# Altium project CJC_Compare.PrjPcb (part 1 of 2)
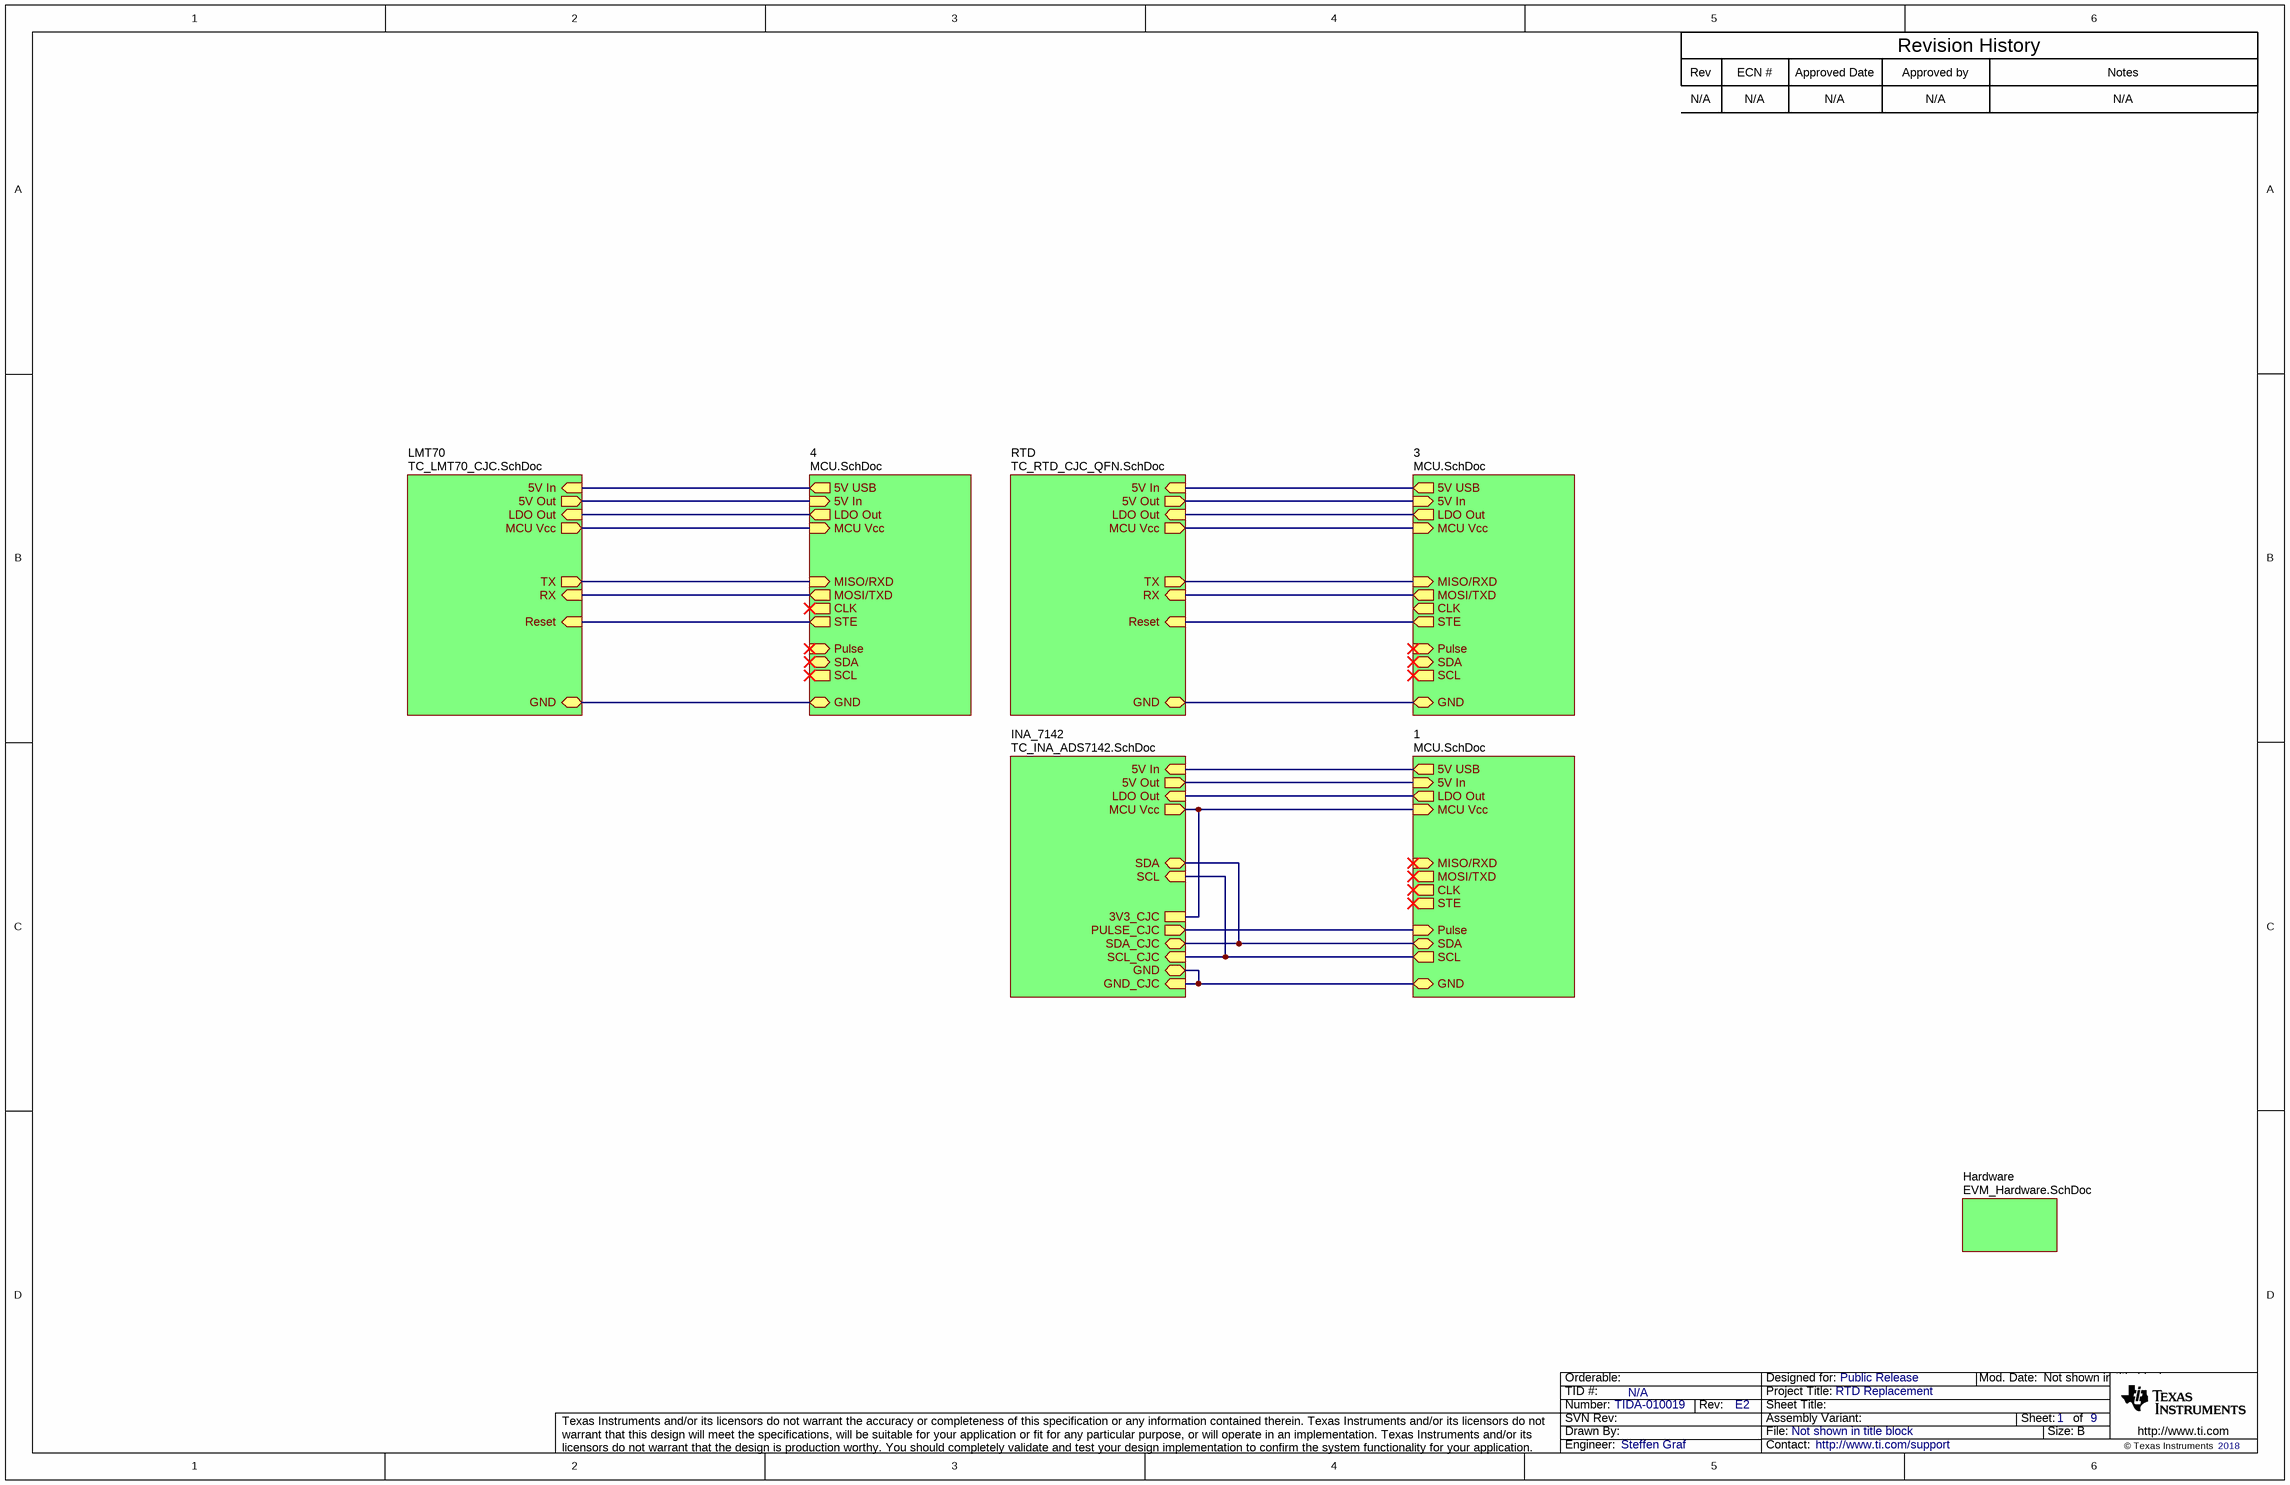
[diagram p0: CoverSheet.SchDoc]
CopyrightYear: 2018; PCB_Layout: SG; PCB_Rev: E2; PRJ_Customer: Public Release; PRJ_Engineer: Steffen Graf; PRJ_Number: TIDA-010019; PRJ_Title: RTD Replacement; SCH_Rev: E2; TechSupport: http://www.ti.com/support; TID: N/A
6 sheets, 304 parts. Net scope: strictly hierarchical (ports join the sheet entries above them; power ports are local).
Board file: TIDA-010019E2.PcbDoc
Sheets:
  CoverSheet.SchDoc
    Hardware = EVM_Hardware.SchDoc
    INA_7142 = TC_INA_ADS7142.SchDoc
    RTD = TC_RTD_CJC_QFN.SchDoc
    LMT70 = TC_LMT70_CJC.SchDoc
    1 = MCU.SchDoc
    3 = MCU.SchDoc
    4 = MCU.SchDoc

## Sheet CoverSheet.SchDoc
size 431 x 279 mm; Date: Not shown in title block; ApprovedBy: Not shown in title block; CheckedBy: Not shown in title block; Author: Not shown in title block; CompanyName: Not shown in title block; Engineer: Not shown in title block; Organization: Not shown in title block; Address1: Not shown in title block; Address2: Not shown in title block; Address3: Not shown in title block; Address4: Not shown in title block; DocumentNumber: 1; Revision: Use project parameter SCH_Rev; SheetNumber: 1; SheetTotal: 9; PageSetup: Record=PageOptions¦CenterHorizontal=True¦CenterVertical=True¦PrintScale=1.00¦XCorrection=1.00¦YCorrection=1.00¦PrintKind=0¦BorderSize=5000000¦LeftOffset=0¦BottomOffset=0¦Orientation=2¦PaperLength=1000¦PaperWidth=1000¦Scale=100¦PaperSource=15¦PrintQuality=600¦MediaType=1¦DitherType=10¦PaperKind=Letter¦PrintScaleMode=1

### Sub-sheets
1 = MCU.SchDoc: SDA (bidir), SCL (out), MISO/RXD (in), MOSI/TXD (out), Pulse (in), STE (out), CLK (out), 5V USB (out), MCU Vcc (in), 5V In (in), LDO Out (out), GND (bidir)
3 = MCU.SchDoc: SDA (bidir), SCL (out), MISO/RXD (in), MOSI/TXD (out), Pulse (in), STE (out), CLK (out), 5V USB (out), MCU Vcc (in), 5V In (in), LDO Out (out), GND (bidir)
4 = MCU.SchDoc: SDA (bidir), SCL (out), MISO/RXD (in), MOSI/TXD (out), Pulse (in), STE (out), CLK (out), 5V USB (out), MCU Vcc (in), 5V In (in), LDO Out (out), GND (bidir)
Hardware = EVM_Hardware.SchDoc: no entries
INA_7142 = TC_INA_ADS7142.SchDoc: SDA_CJC (bidir), GND_CJC (in), PULSE_CJC (out), 3V3_CJC, SDA (bidir), SCL_CJC (in), SCL (in), MCU Vcc (out), LDO Out (in), 5V Out (out), GND (bidir), 5V In (in)
LMT70 = TC_LMT70_CJC.SchDoc: TX (out), RX (in), Reset (in), MCU Vcc (out), LDO Out (in), 5V Out (out), 5V In (in), GND (bidir)
RTD = TC_RTD_CJC_QFN.SchDoc: Reset (in), TX (out), RX (in), LDO Out (in), 5V Out (out), 5V In (in), GND (bidir), MCU Vcc (out)

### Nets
3.3V: sheet INA_7142/3V3_CJC, sheet INA_7142/MCU Vcc, sheet 1/MCU Vcc
3.3V: sheet RTD/MCU Vcc, sheet 3/MCU Vcc  [a separate net that carries the same name]
3.3V: sheet LMT70/MCU Vcc, sheet 4/MCU Vcc  [a separate net that carries the same name]
GND: sheet INA_7142/GND_CJC, sheet INA_7142/GND, sheet 1/GND
GND: sheet RTD/GND, sheet 3/GND  [a separate net that carries the same name]
GND: sheet LMT70/GND, sheet 4/GND  [a separate net that carries the same name]
NetC83_1_1: sheet INA_7142/5V Out, sheet 1/5V In
NetC83_3_1: sheet RTD/5V Out, sheet 3/5V In
NetC83_4_1: sheet LMT70/5V Out, sheet 4/5V In
NetC84_1_1: sheet INA_7142/LDO Out, sheet 1/LDO Out
NetC84_3_1: sheet RTD/LDO Out, sheet 3/LDO Out
NetC84_4_1: sheet LMT70/LDO Out, sheet 4/LDO Out
NetC89_1_1: sheet INA_7142/5V In, sheet 1/5V USB
NetC89_3_1: sheet RTD/5V In, sheet 3/5V USB
NetC89_4_1: sheet LMT70/5V In, sheet 4/5V USB
NetJ8_10: sheet LMT70/TX, sheet 4/MISO/RXD
NetJ8_12: sheet LMT70/RX, sheet 4/MOSI/TXD
NetJ8_14: sheet LMT70/Reset, sheet 4/STE
NetJ22_14: sheet INA_7142/SCL_CJC, sheet INA_7142/SCL, sheet 1/SCL
NetJ24_10: sheet RTD/TX, sheet 3/MISO/RXD
NetJ24_12: sheet RTD/RX, sheet 3/MOSI/TXD
NetJ24_14: sheet RTD/Reset, sheet 3/STE
NetJ36_1: sheet INA_7142/PULSE_CJC, sheet 1/Pulse
NetJ36_2: sheet INA_7142/SDA_CJC, sheet INA_7142/SDA, sheet 1/SDA

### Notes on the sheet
- Rev
- N/A
- ECN #
- Approved Date
- Approved by
- Revision History
- Notes

## Sheet EVM_Hardware.SchDoc
size 431 x 279 mm; Date: Not shown in title block; ApprovedBy: Not shown in title block; CheckedBy: Not shown in title block; Author: Not shown in title block; CompanyName: Not shown in title block; Engineer: Not shown in title block; Organization: Not shown in title block; Address1: Not shown in title block; Address2: Not shown in title block; Address3: Not shown in title block; Address4: Not shown in title block; DocumentNumber: 9; Revision: Use project parameter SCH_Rev; SheetNumber: 9; SheetTotal: 9; PageSetup: Record=PageOptions¦CenterHorizontal=True¦CenterVertical=True¦PrintScale=1.00¦XCorrection=1.00¦YCorrection=1.00¦PrintKind=0¦BorderSize=5000000¦LeftOffset=0¦BottomOffset=0¦Orientation=2¦PaperLength=1000¦PaperWidth=1000¦Scale=100¦PaperSource=15¦PrintQuality=600¦MediaType=1¦DitherType=10¦PaperKind=Letter¦PrintScaleMode=1
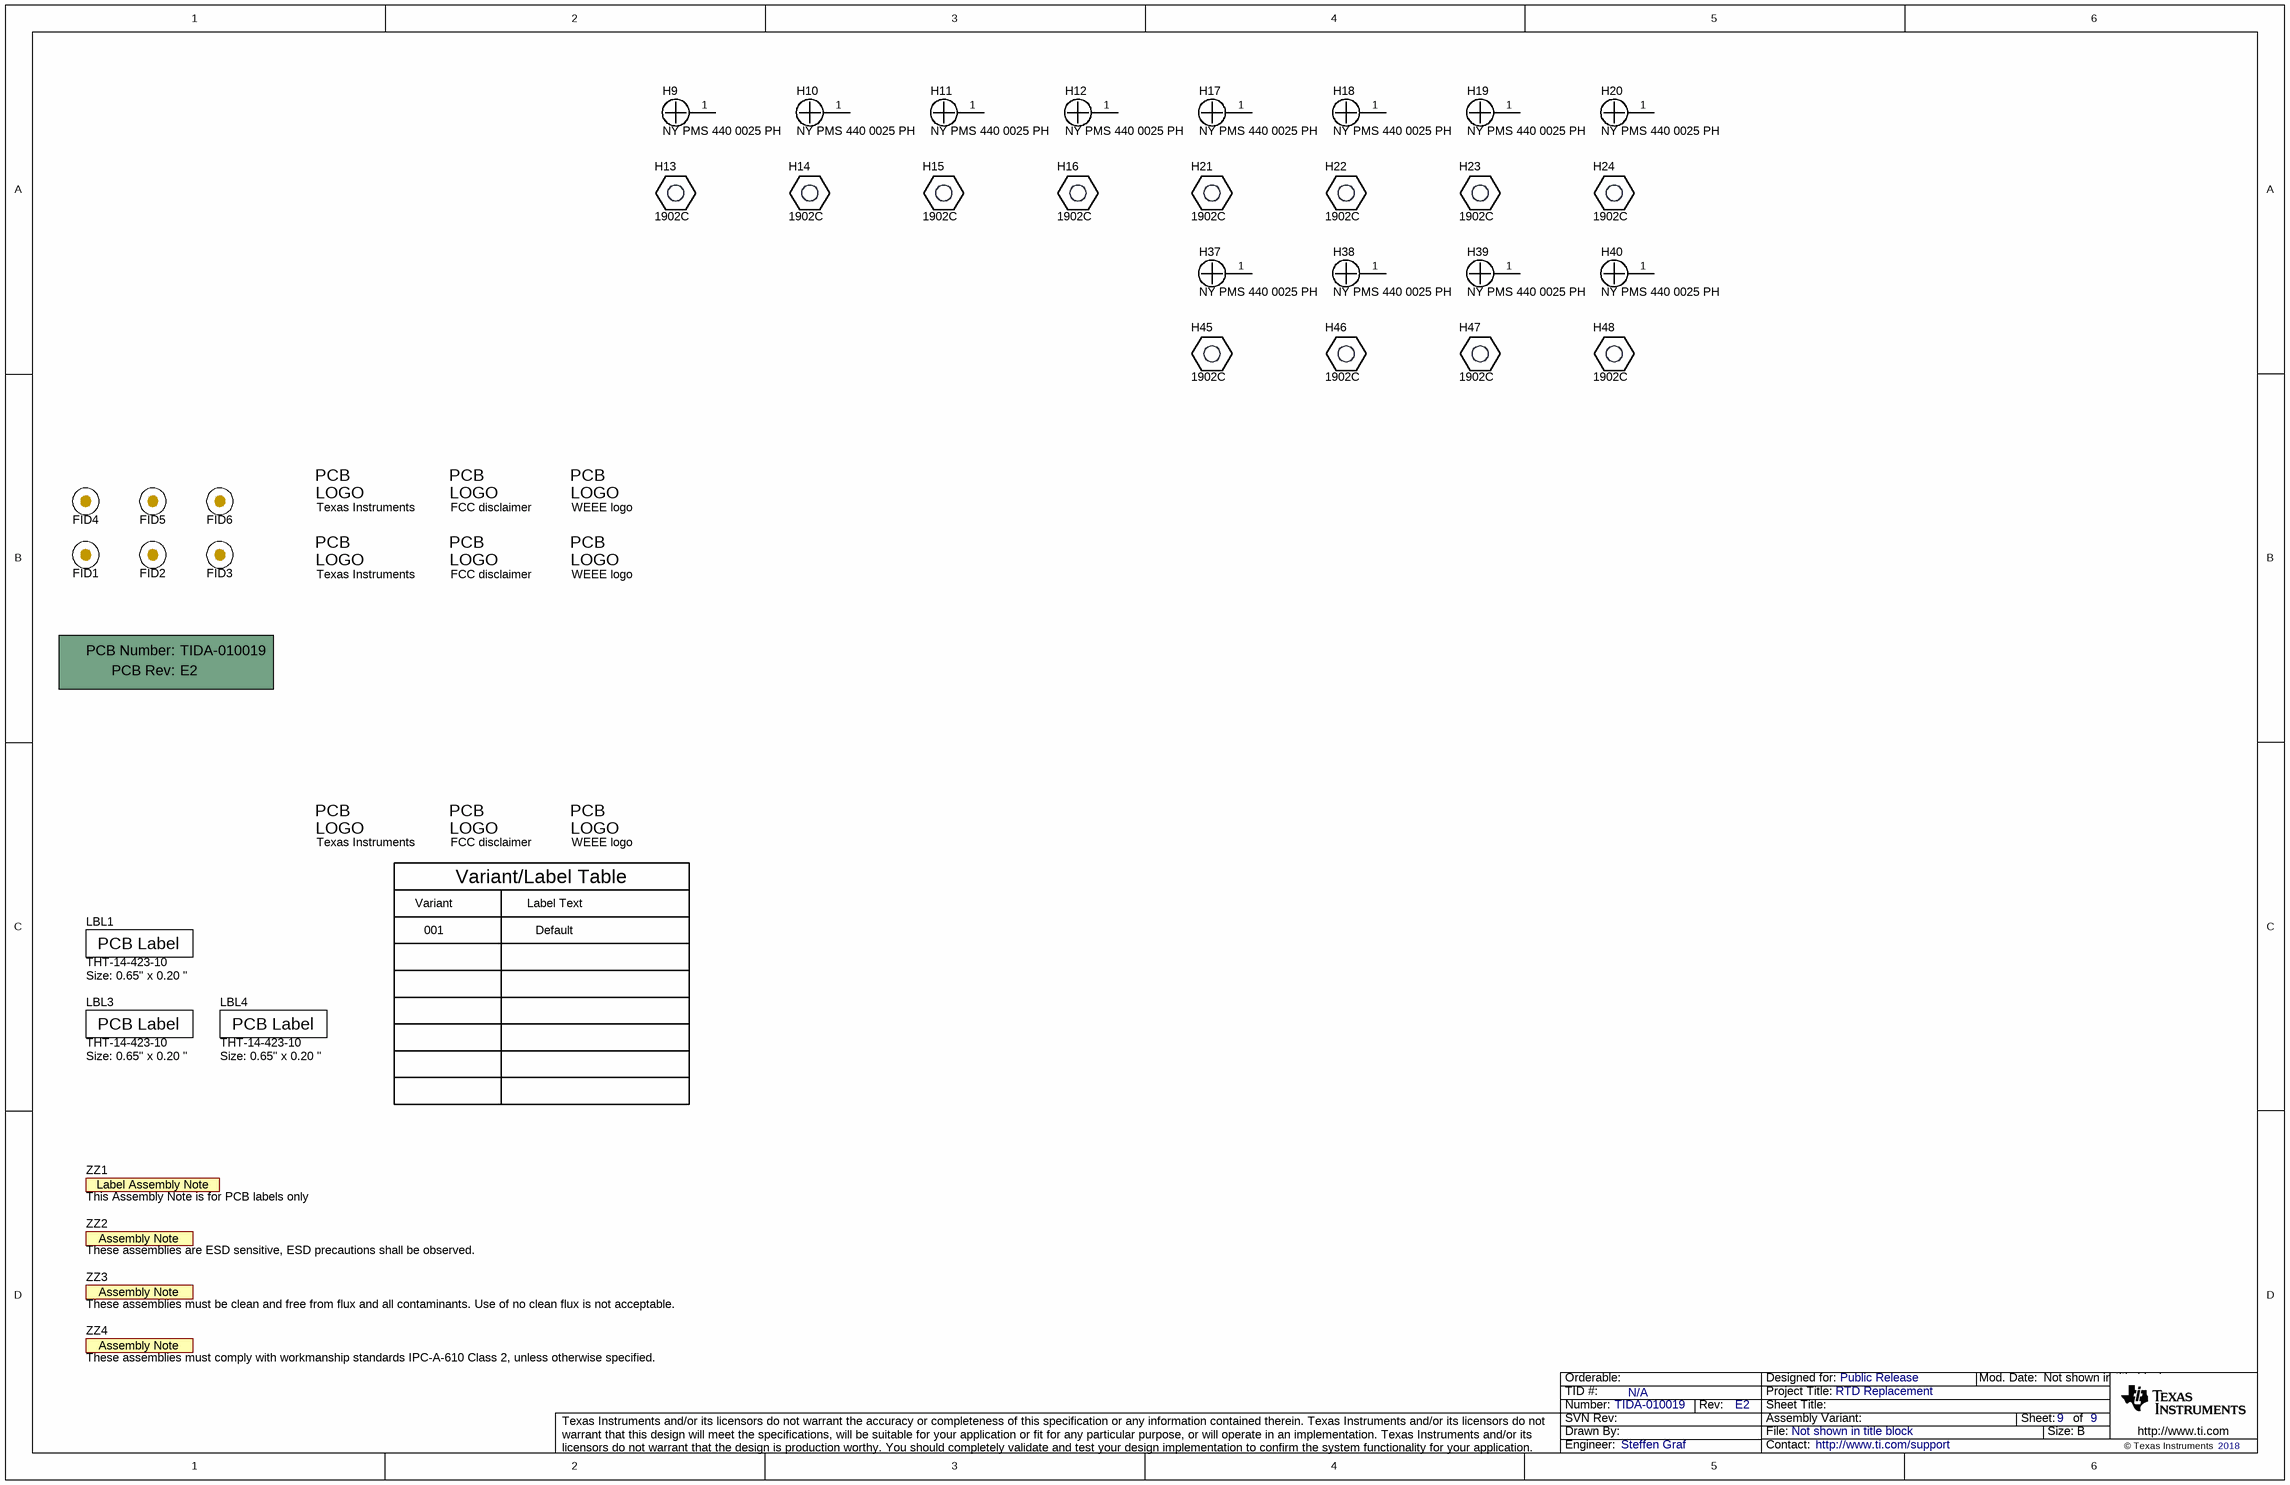
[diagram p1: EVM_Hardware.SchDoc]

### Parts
!PCB  Printed Circuit Board  (value not drawn)  (mechanical)
FID1  Fiducial  [Fiducial10-20]  (value not drawn)
FID2  Fiducial  [Fiducial10-20]  (value not drawn)
FID3  Fiducial  [Fiducial10-20]  (value not drawn)
FID4  Fiducial  [Fiducial10-20]  (value not drawn)
FID5  Fiducial  [Fiducial10-20]  (value not drawn)
FID6  Fiducial  [Fiducial10-20]  (value not drawn)
H9  NY PMS 440 0025 PH  [NY PMS 440 0025 PH]
H10  NY PMS 440 0025 PH  [NY PMS 440 0025 PH]
H11  NY PMS 440 0025 PH  [NY PMS 440 0025 PH]
H12  NY PMS 440 0025 PH  [NY PMS 440 0025 PH]
H13  1902C  [Keystone_1902C]
H14  1902C  [Keystone_1902C]
H15  1902C  [Keystone_1902C]
H16  1902C  [Keystone_1902C]
H17  NY PMS 440 0025 PH  [NY PMS 440 0025 PH]
H18  NY PMS 440 0025 PH  [NY PMS 440 0025 PH]
H19  NY PMS 440 0025 PH  [NY PMS 440 0025 PH]
H20  NY PMS 440 0025 PH  [NY PMS 440 0025 PH]
H21  1902C  [Keystone_1902C]
H22  1902C  [Keystone_1902C]
H23  1902C  [Keystone_1902C]
H24  1902C  [Keystone_1902C]
H37  NY PMS 440 0025 PH  [NY PMS 440 0025 PH]
H38  NY PMS 440 0025 PH  [NY PMS 440 0025 PH]
H39  NY PMS 440 0025 PH  [NY PMS 440 0025 PH]
H40  NY PMS 440 0025 PH  [NY PMS 440 0025 PH]
H45  1902C  [Keystone_1902C]
H46  1902C  [Keystone_1902C]
H47  1902C  [Keystone_1902C]
H48  1902C  [Keystone_1902C]
LBL1  THT-14-423-10  Note: Size: 0.65" x 0.20 "  [Label_650x200]
LBL3  THT-14-423-10  Note: Size: 0.65" x 0.20 "  [Label_650x200]
LBL4  THT-14-423-10  Note: Size: 0.65" x 0.20 "  [Label_650x200]
Logo1  Texas Instruments  [TI_Stacked_Overlay_Small]  (no BOM)
Logo2  Texas Instruments  [TI_Stacked_Overlay_Small]  (no BOM)
Logo3  FCC disclaimer  [FCC_disclaimer]  (no BOM)
Logo4  WEEE logo  [WEEE_Minimum]  (no BOM)
Logo5  FCC disclaimer  [FCC_disclaimer]  (no BOM)
Logo6  WEEE logo  [WEEE_Minimum]  (no BOM)
Logo16  Texas Instruments  [TI_Stacked_Overlay_Small]  (no BOM)
Logo17  FCC disclaimer  [FCC_disclaimer]  (no BOM)
Logo18  WEEE logo  [WEEE_Minimum]  (no BOM)
ZZ1  This Assembly Note is for PCB labels only  [AssemblyNoteLabel]  (no BOM)
ZZ2  These assemblies are ESD sensitive, ESD precautions shall be observed.  [AssemblyNote]  (no BOM)
ZZ3  These assemblies must be clean and free from flux and all contaminants. Use of no clean flux is not acceptable.  [AssemblyNote]  (no BOM)
ZZ4  These assemblies must comply with workmanship standards IPC-A-610 Class 2, unless otherwise specified.  [AssemblyNote]  (no BOM)

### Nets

Not connected (* = marked no-connect by the designer): H9 1; H10 1; H11 1; H12 1; H17 1; H18 1; H19 1; H20 1; H37 1; H38 1; H39 1; H40 1

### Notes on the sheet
- Variant
- Variant/Label Table
- Label Text
- 001
- Default

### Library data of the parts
!PCB = CMP-0003618-2: Manufacturer: Any; PartNumber: TIDA-010019
FID1-FID6 = CMP-0077181-1: Fiducial mark.  There is nothing to buy or mount.
H9-H12 H17-H20 H37-H40 = CMP-0003617-1: Machine Screw, Round, #4-40 x 1/4, Nylon, Philips panhead; Manufacturer: B&F Fastener Supply; CompType: Hardware
H13-H16 H21-H24 H45-H48 = CMP-0003610-1: Standoff, Hex, 0.5"L #4-40 Nylon; Manufacturer: Keystone; CompType: Hardware
LBL1 LBL3 LBL4 = CMP-0003625-1: Thermal Transfer Printable Labels, 0.650" W x 0.200" H - 10,000 per roll; Manufacturer: Brady; CompType: Label
Logo1 Logo2 Logo16 = CMP-0074838-1: Texas Instrument Corporate Signature; SymbolCreator: a0412235; Lib Reference: TI_Logo; Library Reference: Logo
Logo3 Logo5 Logo17 = CMP-0074847-1: FCC_disclaimer; Library Reference: Logo
Logo4 Logo6 Logo18 = CMP-0074769-1
ZZ1 = CMP-0003616-3
ZZ2 = CMP-0077236-1
ZZ3 = CMP-0077237-1
ZZ4 = CMP-0077238-1

## Sheet TC_INA_ADS7142.SchDoc
size 431 x 279 mm; Date: Not shown in title block; ApprovedBy: Not shown in title block; CheckedBy: Not shown in title block; Author: Not shown in title block; CompanyName: Not shown in title block; Engineer: Not shown in title block; Organization: Not shown in title block; Address1: Not shown in title block; Address2: Not shown in title block; Address3: Not shown in title block; Address4: Not shown in title block; DocumentNumber: 5; Revision: Use project parameter SCH_Rev; SheetNumber: 5; SheetTotal: 9; PageSetup: Record=PageOptions¦CenterHorizontal=True¦CenterVertical=True¦PrintScale=1.00¦XCorrection=1.00¦YCorrection=1.00¦PrintKind=0¦BorderSize=5000000¦LeftOffset=0¦BottomOffset=0¦Orientation=2¦PaperLength=1000¦PaperWidth=1000¦Scale=100¦PaperSource=15¦PrintQuality=600¦MediaType=1¦DitherType=10¦PaperKind=Letter¦PrintScaleMode=1
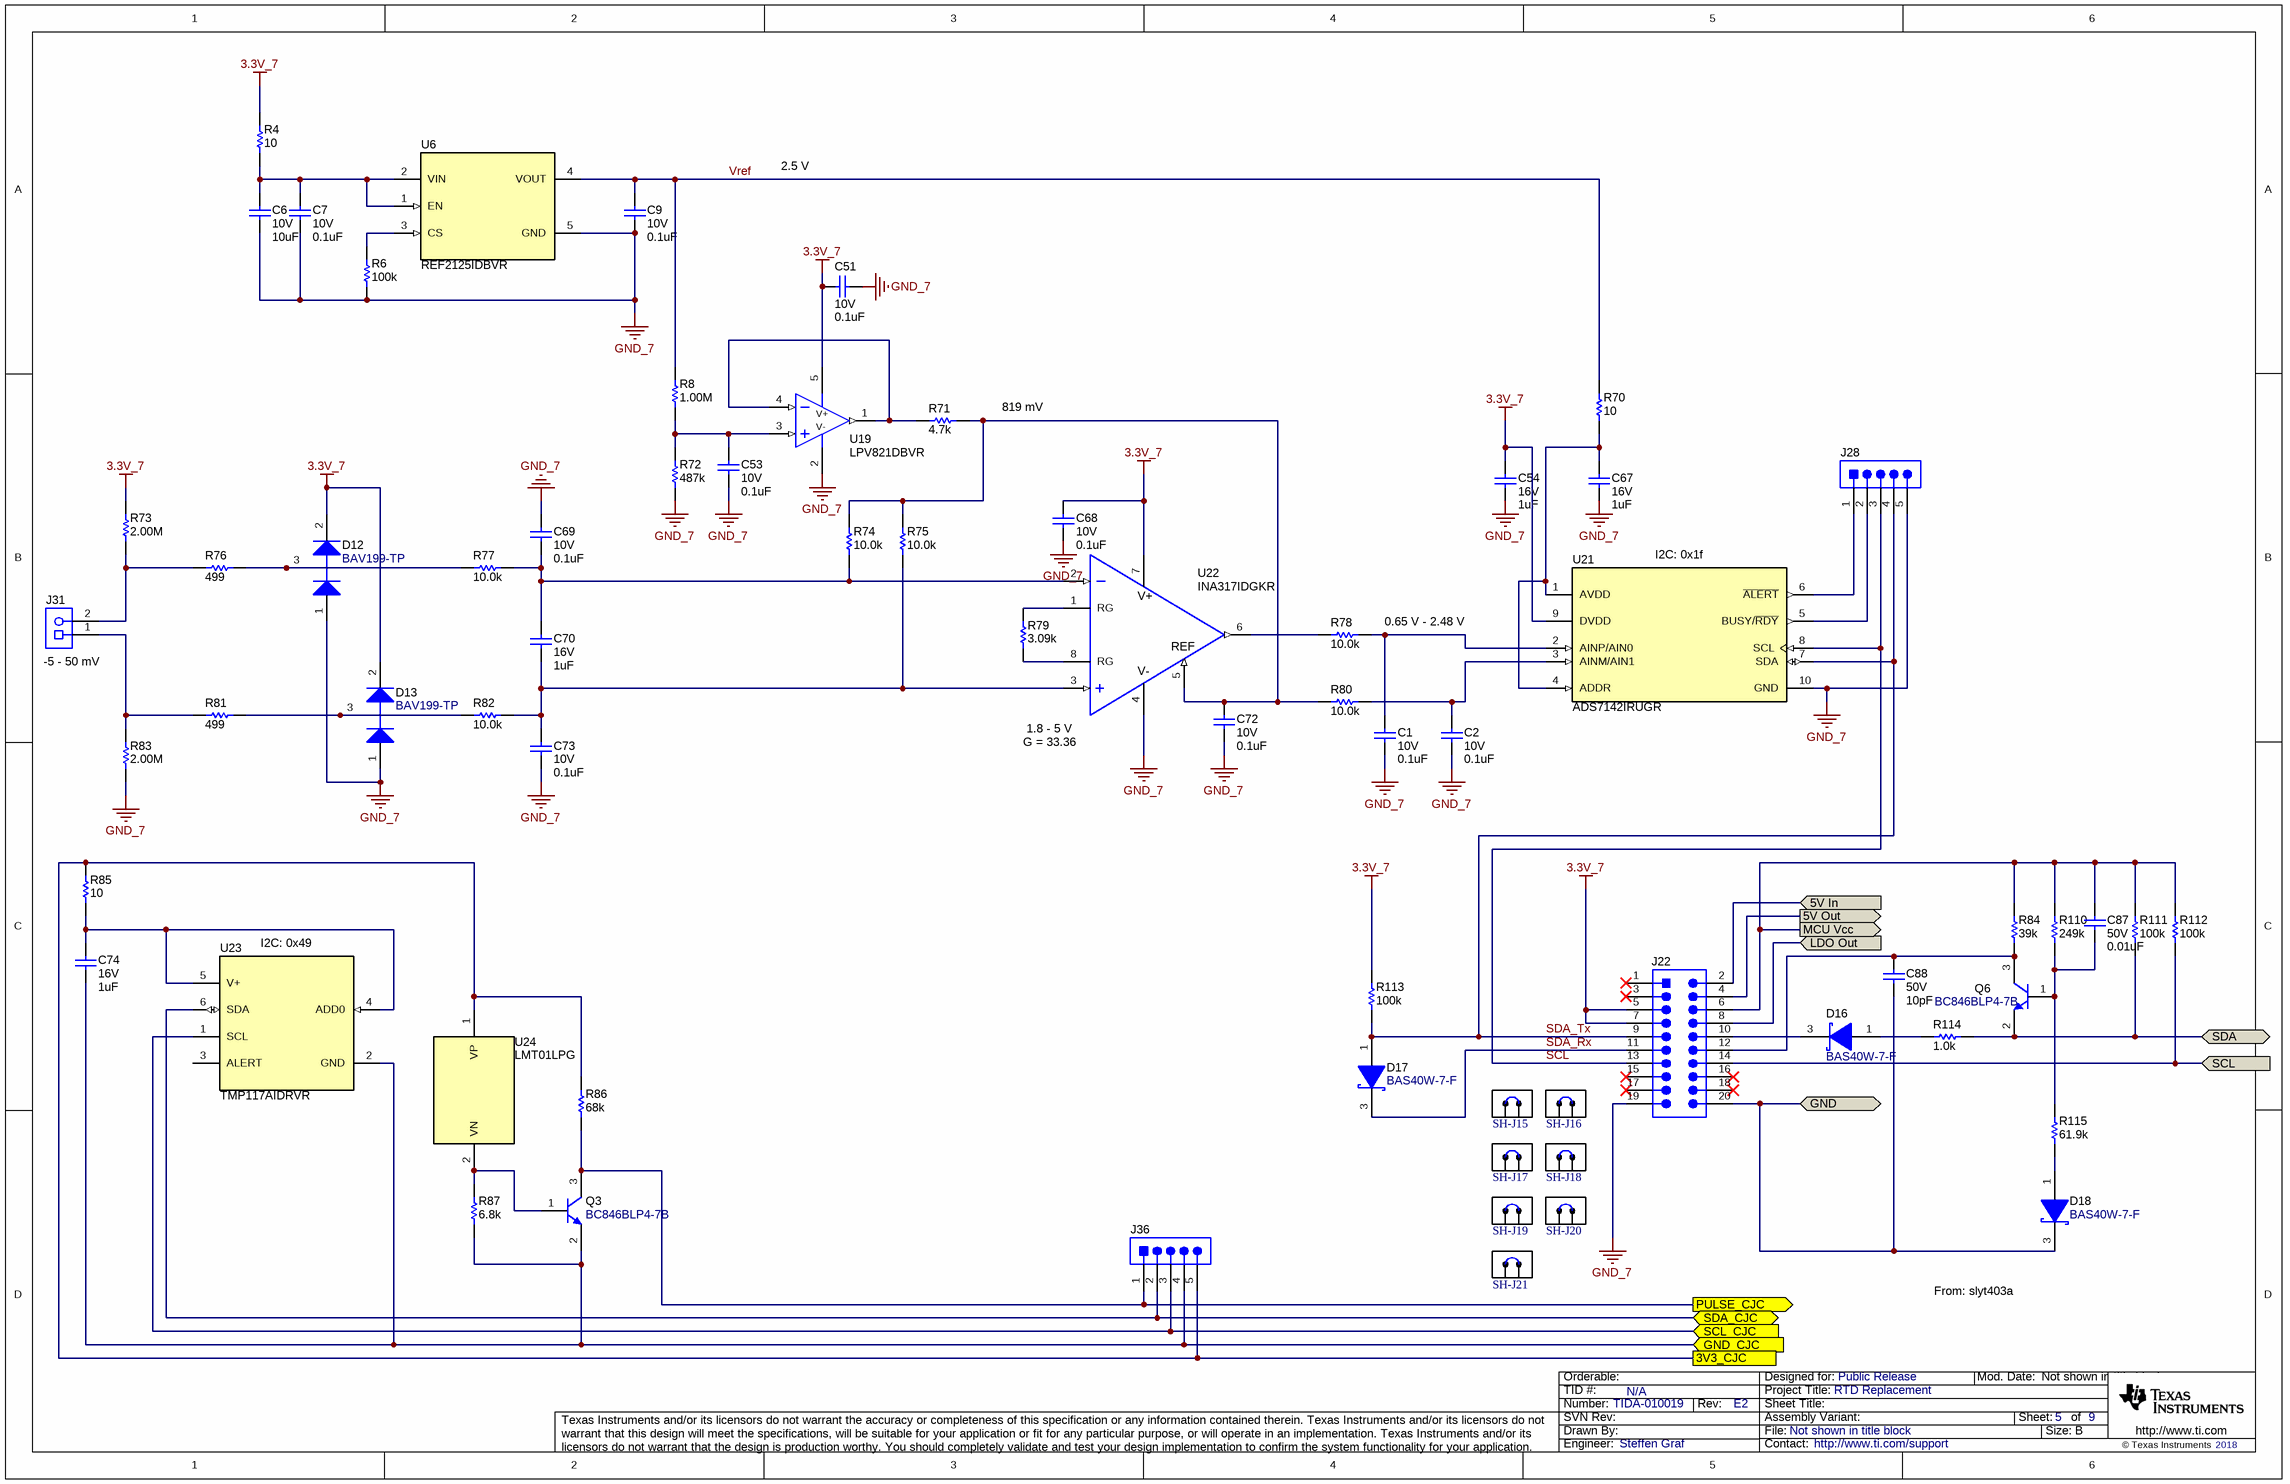
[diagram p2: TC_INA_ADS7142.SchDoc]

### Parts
C1  VDC_V: 10V  ValueDisplayed: 0.1uF  [0603]  (hidden comment: 885012206020)
C2  VDC_V: 10V  ValueDisplayed: 0.1uF  [0603]  (hidden comment: 885012206020)
C6  VDC_V: 10V  ValueDisplayed: 10uF  [0805_HV]  (hidden comment: 885012207026)
C7  VDC_V: 10V  ValueDisplayed: 0.1uF  [0603]  (hidden comment: 885012206020)
C9  VDC_V: 10V  ValueDisplayed: 0.1uF  [0603]  (hidden comment: 885012206020)
C51  VDC_V: 10V  ValueDisplayed: 0.1uF  [0603]  (hidden comment: 885012206020)
C53  VDC_V: 10V  ValueDisplayed: 0.1uF  [0603]  (hidden comment: 885012206020)
C54  VDC_V: 16V  ValueDisplayed: 1uF  [0603]  (hidden comment: 885012106017)
C67  VDC_V: 16V  ValueDisplayed: 1uF  [0603]  (hidden comment: 885012106017)
C68  VDC_V: 10V  ValueDisplayed: 0.1uF  [0603]  (hidden comment: 885012206020)
C69  VDC_V: 10V  ValueDisplayed: 0.1uF  [0603]  (hidden comment: 885012206020)
C70  VDC_V: 16V  ValueDisplayed: 1uF  [0603]  (hidden comment: GCM188R71C105MA64D)
C72  VDC_V: 10V  ValueDisplayed: 0.1uF  [0603]  (hidden comment: 885012206020)
C73  VDC_V: 10V  ValueDisplayed: 0.1uF  [0603]  (hidden comment: 885012206020)
C74  VDC_V: 16V  ValueDisplayed: 1uF  [0603]  (hidden comment: 885012106017)
C87  VDC_V: 50V  ValueDisplayed: 0.01uF  [0402]  (hidden comment: GCM155R71H103KA55D)
C88  VDC_V: 50V  ValueDisplayed: 10pF  [0402]  (hidden comment: 885012005055)
D12  BAV199-TP  [SOT-23L]
D13  BAV199-TP  [SOT-23L]
D16  BAS40W-7-F  [SOT-323]
D17  BAS40W-7-F  [SOT-323]
D18  BAS40W-7-F  [SOT-323]
J22  PRPC010DAAN-RC  [Sullins_xxxC010DAAN]  (value not drawn)
J28  61300511121  [Wurth_61300511121]  (value not drawn)
J31  691210910002  [Wurth_691210910002]  (value not drawn)
J36  61300511121  [Wurth_61300511121]  (value not drawn)
Q3  BC846BLP4-7B  [X2-DFN1006-3]
Q6  BC846BLP4-7B  [X2-DFN1006-3]
R4  ValueDisplayed: 10  [0402]  (hidden comment: CRCW040210R0JNED)
R6  ValueDisplayed: 100k  [0402]  (hidden comment: CRCW0402100KFKED)
R8  ValueDisplayed: 1.00M  [0603]  (hidden comment: RMCF0603FG1M00)
R70  ValueDisplayed: 10  [0402]  (hidden comment: CRCW040210R0JNED)
R71  ValueDisplayed: 4.7k  [0402]  (hidden comment: CRCW04024K70JNED)
R72  ValueDisplayed: 487k  [0603]  (hidden comment: CRCW0603487KFKEA)
R73  ValueDisplayed: 2.00M  [0402]  (hidden comment: CRCW04022M00FKED)
R74  ValueDisplayed: 10.0k  [0603]  (hidden comment: CRCW060310K0FKEA)
R75  ValueDisplayed: 10.0k  [0603]  (hidden comment: CRCW060310K0FKEA)
R76  ValueDisplayed: 499  [0402]  (hidden comment: CRCW0402499RFKED)
R77  ValueDisplayed: 10.0k  [0402]  (hidden comment: CRCW040210K0FKED)
R78  ValueDisplayed: 10.0k  [0603]  (hidden comment: CRCW060310K0FKEA)
R79  ValueDisplayed: 3.09k  [0603]  (hidden comment: CRCW06033K09FKEA)
R80  ValueDisplayed: 10.0k  [0603]  (hidden comment: CRCW060310K0FKEA)
R81  ValueDisplayed: 499  [0402]  (hidden comment: CRCW0402499RFKED)
R82  ValueDisplayed: 10.0k  [0402]  (hidden comment: CRCW040210K0FKED)
R83  ValueDisplayed: 2.00M  [0402]  (hidden comment: CRCW04022M00FKED)
R84  ValueDisplayed: 39k  [0402S]  (hidden comment: CRCW040239K0JNED)
R85  ValueDisplayed: 10  [0402]  (hidden comment: CRCW040210R0JNED)
R86  ValueDisplayed: 68k  [0402]  (hidden comment: CRCW040268K0JNED)
R87  ValueDisplayed: 6.8k  [0402]  (hidden comment: CRCW04026K80JNED)
R110  ValueDisplayed: 249k  [0402]  (hidden comment: CRCW0402249KFKED)
R111  ValueDisplayed: 100k  [0402]  (hidden comment: CRCW0402100KJNED)
R112  ValueDisplayed: 100k  [0402]  (hidden comment: CRCW0402100KJNED)
R113  ValueDisplayed: 100k  [0402]  (hidden comment: CRCW0402100KJNED)
R114  ValueDisplayed: 1.0k  [0402]  (hidden comment: CRCW04021K00JNED)
R115  ValueDisplayed: 61.9k  [0402]  (hidden comment: CRCW040261K9FKED)
SH-J15  60900213421  [Wurth_60900213421]  (value not drawn)
SH-J16  60900213421  [Wurth_60900213421]  (value not drawn)
SH-J17  60900213421  [Wurth_60900213421]  (value not drawn)
SH-J18  60900213421  [Wurth_60900213421]  (value not drawn)
SH-J19  60900213421  [Wurth_60900213421]  (value not drawn)
SH-J20  60900213421  [Wurth_60900213421]  (value not drawn)
SH-J21  60900213421  [Wurth_60900213421]  (value not drawn)
U6  REF2125IDBVR  [DBV0005A_N]
U19  LPV821DBVR  [DBV0005A_N]
U21  ADS7142IRUGR  [RUG0010A]
U22  INA317IDGKR  [DGK0008A_N]
U23  TMP117AIDRVR  [DRV0006B]
U24  LMT01LPG  [LPG0002A]

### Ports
3V3_CJC, 5V In (in), 5V Out (out), GND (bidir), GND_CJC (in), LDO Out (in), MCU Vcc (out), PULSE_CJC (out), SCL (in), SCL_CJC (in), SDA (bidir), SDA_CJC (bidir)

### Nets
3.3V: C87.1 J22.6 J36.5 R84.2 R85.1 R86.2 R110.2 R111.2 R112.2 U24.1(VP) ; port 3V3_CJC, port MCU Vcc
3.3V_7: C51.1 C54.1 C68.1 D12.2(K) D13.2(K) J22.5 J22.7 R4.2 R73.2 R113.2 U19.5(V+) U21.9(DVDD) U22.7(V+)
GND: C74.2 C88.2 D18.3(K) J22.20 J36.4 Q3.2(E) R87.1 U23.2(GND) ; port GND_CJC, port GND
GND_7: C1.2 C2.2 C6.2 C7.2 C9.2 C51.2 C53.2 C54.2 C67.2 C68.2 C69.1 C72.2 C73.2 D12.1(A) D13.1(A) J22.19 J28.5 R6.1 R72.1 R83.1 U6.5(GND) U19.2(V-) U21.10(GND) U22.4(V-)
SCL: J22.13 J28.3 U21.8(SCL)  [project net SCL_5]
SDA_Rx: D17.3(K) J22.11  [project net SDA_Rx_5]
SDA_Tx: D17.1(A) J22.9 J28.4 R113.1 U21.7(SDA)  [project net SDA_Tx_5]
Vref: C9.1 R8.2 R70.2 U6.4(VOUT)  [project net Vref_5]
NetC1_1: C1.1 R78.2 U21.2(AINP/AIN0)
NetC2_1: C2.1 R80.2 U21.3(AINM/AIN1)
NetC6_1: C6.1 C7.1 R4.1 U6.1(EN) U6.2(VIN)
NetC53_1: C53.1 R8.1 R72.2 U19.3(IN+)
NetC67_1: C67.1 R70.1 U21.1(AVDD) U21.4(ADDR)
NetC69_2: C69.2 C70.1 R74.1 R77.1 U22.2(IN-)
NetC70_2: C70.2 C73.1 R75.1 R82.1 U22.3(IN+)
NetC72_1: C72.1 R71.1 R74.2 R75.2 R80.1 U22.5(REF)
NetC74_1: C74.1 R85.2 U23.4(ADD0) U23.5(V+)
NetC83_1_1: J22.4 ; port 5V Out
NetC84_1_1: J22.8 ; port LDO Out
NetC87_2: C87.2 Q6.1(B) R110.1 R115.2
NetC88_1: C88.1 J22.12 Q6.3(C) R84.1
NetC89_1_1: J22.2 ; port 5V In
NetD12_3: D12.3(C) R76.1 R77.2
NetD13_3: D13.3(C) R81.1 R82.2
NetD16_1: D16.1(A) R114.1
NetD16_3: D16.3(K) J22.10
NetD18_1: D18.1(A) R115.1
NetJ22_14: J22.14 J36.3 R112.1 U23.1(SCL) ; port SCL_CJC, port SCL
NetJ28_1: J28.1 U21.6(~{ALERT})
NetJ28_2: J28.2 U21.5(BUSY/~{RDY})
NetJ31_1: J31.1 R81.2 R83.2
NetJ31_2: J31.2 R73.1 R76.2
NetJ36_1: J36.1 Q3.3(C) R86.1 ; port PULSE_CJC
NetJ36_2: J36.2 Q6.2(E) R111.1 R114.2 U23.6(SDA) ; port SDA_CJC, port SDA
NetQ3_1: Q3.1(B) R87.2 U24.2(VN)
NetR6_2: R6.2 U6.3(CS)
NetR71_2: R71.2 U19.1(OUT) U19.4(IN-)
NetR78_1: R78.1 U22.6(OUT)
NetR79_1: R79.1 U22.8(RG)
NetR79_2: R79.2 U22.1(RG)

Not connected (* = marked no-connect by the designer): J22 1* 3* 15* 16* 17* 18*; U23 3(ALERT)

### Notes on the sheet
- 2.5 V
- (near R71) 819 mV
- (near U21) I2C: 0x1f
- (near R78) 0.65 V - 2.48 V
- (near J31) -5 - 50 mV
- (near U22) 1.8 - 5 V
- (near U22) G = 33.36
- (near U23) I2C: 0x49
- From: slyt403a

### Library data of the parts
C1 C2 C7 C9 C51 C53 C68 C69 C72 C73 = CMP-0064931-4: CAP, CERM, 0.1 uF, 10 V,+/- 10%, X7R, 0603; Manufacturer: Wurth Elektronik; TaMin_C: -55°C; Polarized: N; SizeAreaWB_mm2: 4.68; Value1: Unknown; U/M: EA; Value: 0.1uF; TaMax_C: 125°C; SizeZ_mm: 1; SizeX_mm: 1.6; SizeY_mm: 0.8; SizeArea_mm2: 1.28; Cap_F: 100nF; AEC Category: Q200
C6 = CMP-0007691-2: CAP, CERM, 10 uF, 10 V, +/- 10%, X7R, 0805; Manufacturer: Wurth Elektronik; TaMin_C: -55°C; Polarized: N; SizeAreaWB_mm2: 6.75; Value1: Unknown; U/M: EA; Value: 10uF; TaMax_C: 125°C; SizeZ_mm: 1.45; SizeX_mm: 2; SizeY_mm: 1.25; Cap_Case: 0805; SizeArea_mm2: 2.5; Cap_F: 10µF; AEC Category: Q200
C54 C67 C74 = CMP-0006824-5: CAP, CERM, 1 uF, 16 V, +/- 20%, X5R, 0603; Manufacturer: Wurth Elektronik; TaMin_C: -55°C; Polarized: N; SizeAreaWB_mm2: 4.68; Value1: Unknown; U/M: EA; Value: 1uF; TaMax_C: 85°C; SizeZ_mm: 1; SizeX_mm: 1.6; SizeY_mm: 0.8; SizeArea_mm2: 1.28; Cap_F: 1µF; AEC Category: Q200
C70 = CMP-0007137-5: CAP, CERM, 1 uF, 16 V, +/- 20%, X7R, AEC-Q200 Grade 1, 0603; Manufacturer: MuRata; TaMin_C: -55°C; Polarized: N; SizeAreaWB_mm2: 4.68; Value1: Unknown; U/M: EA; Value: 1uF; TaMax_C: 125°C; SizeZ_mm: 1; SizeX_mm: 1.6; SizeY_mm: 0.8; SizeArea_mm2: 1.28; AEC Qualified: Y; Cap_F: 1µF; AEC Category: Q200
C87 = CMP-0006355-2: CAP, CERM, 0.01 uF, 50 V, +/- 10%, C0G/NP0, 0402; Manufacturer: MuRata; TaMin_C: -55°C; Polarized: N; SizeAreaWB_mm2: 3; Value1: Unknown; U/M: EA; Value: 0.01uF; TaMax_C: 125°C; SizeZ_mm: 0.6; SizeX_mm: 1; SizeY_mm: 0.5; Cap_F: 10nF; AEC Category: Q200
C88 = CMP-0006215-2: CAP, CERM, 10 pF, 50 V, +/- 5%, C0G/NP0, 0402; Manufacturer: Wurth Elektronik; TaMin_C: -55°C; Polarized: N; SizeAreaWB_mm2: 3; Value1: Unknown; U/M: EA; Value: 10pF; TaMax_C: 125°C; SizeZ_mm: 0.6; SizeX_mm: 1; SizeY_mm: 0.5; AEC Category: Q200
D12 D13 = CMP-0076968-2: Diode, Switching, 70 V, 0.215 A, SOT-23; Manufacturer: Micro Commercial Components; SizeAreaWB_mm2: 14.0; Vr_V: 70V; SizeArea_mm2: 7.5; TJmax_C: 150°C; AEC Category: Q101; Value: 70V; SizeZ_mm: 1.1; Green_REACh: Incomplete; Io_A: 215mA; SizeY_mm: 3.0; Green_Lifecycle: Not Set; Value1: 0.215A; SizeX_mm: 2.5
D16-D18 = CMP-0028438-2: Diode, Schottky, 40 V, 0.2 A, SOT-323; Manufacturer: Diodes Inc.; Value: 40V; Value2: 0.9V; SizeArea_mm2: 4.84; Vf_V: 900mV; Value1: 0.2A; Green_Lifecycle: Not Set; SizeAreaWB_mm2: 10.24; SizeX_mm: 2.2; AEC Category: Q101; Io_A: 200mA; Green_REACh: Incomplete; SizeZ_mm: 1.1
J22 = CMP-0054591-2: Header, 2.54mm, 10x2, Gold, TH; Manufacturer: Sullins Connector Solutions; Shrouded: N; Gender: Male; Row_Count: 2; RowSpacing_mm: 2.54
J28 J36 = CMP-0084909-1: Header, 2.54mm, 5x1, Gold, TH; Manufacturer: Wurth Elektronik; Current_A: 3A; Gender: Male; Pitch_mm: 2.54; Row_Count: 1; Shrouded: N; Voltage_V: 250V
J31 = CMP-0082072-1: Receptacle, 2.54mm, 2x1, Tin, R/A, TH; Manufacturer: Wurth Elektronik; Cert_CULUS: Y; Current_A: 6A; Gender: Female; Pitch_mm: 2.54; Row_Count: 1; Voltage_V: 150V
Q3 = CMP-0082028-2: Transistor, NPN, 65 V, 0.1 A, AEC-Q101, 1x0.6mm; Manufacturer: Diodes Inc.; SizeAreaWB_mm2: 3.2; NPN: 1; SizeArea_mm2: 0.6; AEC Qualified: Y; IcRated_A: 100mA; AEC Category: Q101; Value: 65 V; TaMax_C: 150°C; SizeZ_mm: 0.4; PNP: 0; Vceo_V: 65V; TaMin_C: -55°C; Value2: 450; Value1: 0.1 A; CompType: BJT; Vcesat1_V: 600mV
Q6 = CMP-0082028-2: Transistor, NPN, 65 V, 0.1 A, AEC-Q101, 1x0.6mm; Manufacturer: Diodes Inc.; SizeArea_mm2: 0.6; Vceo_V: 65V; NPN: 1; IcRated_A: 100mA; SizeZ_mm: 0.4; AEC Qualified: Y; Value2: 450; AEC Category: Q101; SizeAreaWB_mm2: 3.2; CompType: BJT; TaMax_C: 150°C; Value: 65 V; Value1: 0.1 A; Vcesat1_V: 600mV; PNP: 0; TaMin_C: -55°C
R4 R70 R85 = CMP-0026827-3: RES, 10, 5%, 0.063 W, AEC-Q200 Grade 0, 0402; Manufacturer: Vishay-Dale; Power_W: 63mW; TempCo: 200 ppm/C; Value_Code: 10R0; Value: 10; EIA_Code: E24; SizeX_mm: 1; SizeY_mm: 0.5; SizeZ_mm: 0.6; Value2: 0.063W; AEC Qualified: Y; VDC_V: 50V; AEC Category: Q200; AEC Grade: 0
R6 = CMP-0025950-3: RES, 100 k, 1%, 0.063 W, AEC-Q200 Grade 0, 0402; Manufacturer: Vishay-Dale; Power_W: 63mW; TempCo: 100 ppm/C; Value: 100k; EIA_Code: E96; SizeX_mm: 1; SizeY_mm: 0.5; SizeZ_mm: 0.6; Value2: 0.063W; AEC Qualified: Y; VDC_V: 50V; AEC Category: Q200; AEC Grade: 0
R8 = CMP-0085900-1: RES, 1.00 M, 1%, 0.1 W, AEC-Q200 Grade 0, 0603; Manufacturer: Stackpole Electronics Inc; Power_W: 100mW; TempCo: 100 ppm/C; Value_Code: 1M00; Value: 1.00Meg; EIA_Code: E96; Res_ohm: 1M; SizeX_mm: 1.6; SizeY_mm: 0.8; SizeZ_mm: 1; Value2: 0.1W; SizeArea_mm2: 1.28; AEC Qualified: Y; AEC Category: Q200; AEC Grade: 0; SizeAreaWB_mm2: 4.68
R71 = CMP-0026938-5: RES, 4.7 k, 5%, 0.063 W, AEC-Q200 Grade 0, 0402; Manufacturer: Vishay-Dale; Power_W: 63mW; TempCo: 200 ppm/C; Value_Code: 4k70; Value: 4.7k; EIA_Code: E24; SizeX_mm: 1; SizeY_mm: 0.5; SizeZ_mm: 0.6; Value2: 0.063W; AEC Qualified: Y; VDC_V: 50V; AEC Category: Q200; AEC Grade: 0
R72 = CMP-0022441-4: RES, 487 k, 1%, 0.1 W, AEC-Q200 Grade 0, 0603; Manufacturer: Vishay-Dale; Power_W: 100mW; TempCo: 100 ppm/C; Value: 487k; EIA_Code: E96; SizeX_mm: 1.6; SizeY_mm: 0.8; SizeZ_mm: 1; Value2: 0.1W; SizeArea_mm2: 1.28; AEC Qualified: Y; VDC_V: 75V; AEC Category: Q200; AEC Grade: 0
R73 R83 = CMP-0026245-2: RES, 2.00 M, 1%, 0.063 W, AEC-Q200 Grade 0, 0402; Manufacturer: Vishay-Dale; Power_W: 63mW; TempCo: 100 ppm/C; Value_Code: 2M00; Value: 2.00Meg; EIA_Code: E96; Res_ohm: 2M; SizeX_mm: 1; SizeY_mm: 0.5; SizeZ_mm: 0.6; Value2: 0.063W; AEC Qualified: Y; VDC_V: 50V; AEC Category: Q200; AEC Grade: 0
R74 R75 R78 R80 = CMP-0021998-4: RES, 10.0 k, 1%, 0.1 W, AEC-Q200 Grade 0, 0603; Manufacturer: Vishay-Dale; Power_W: 100mW; TempCo: 100 ppm/C; Value_Code: 10k0; Value: 10.0k; EIA_Code: E96; Res_ohm: 10k; SizeX_mm: 1.6; SizeY_mm: 0.8; SizeZ_mm: 1; Value2: 0.1W; SizeArea_mm2: 1.28; AEC Qualified: Y; VDC_V: 75V; AEC Category: Q200; AEC Grade: 0
R76 R81 = CMP-0026402-2: RES, 499, 1%, 0.063 W, AEC-Q200 Grade 0, 0402; Manufacturer: Vishay-Dale; Power_W: 63mW; TempCo: 100 ppm/C; Value_Code: 499R; Value: 499; EIA_Code: E96; SizeX_mm: 1; SizeY_mm: 0.5; SizeZ_mm: 0.6; Value2: 0.063W; AEC Qualified: Y; VDC_V: 50V; AEC Category: Q200; AEC Grade: 0
R77 R82 = CMP-0025958-3: RES, 10.0 k, 1%, 0.063 W, AEC-Q200 Grade 0, 0402; Manufacturer: Vishay-Dale; Power_W: 63mW; TempCo: 100 ppm/C; Value_Code: 10k0; Value: 10.0k; EIA_Code: E96; Res_ohm: 10k; SizeX_mm: 1; SizeY_mm: 0.5; SizeZ_mm: 0.6; Value2: 0.063W; AEC Qualified: Y; VDC_V: 50V; AEC Category: Q200; AEC Grade: 0
R79 = CMP-0022372-4: RES, 3.09 k, 1%, 0.1 W, AEC-Q200 Grade 0, 0603; Manufacturer: Vishay-Dale; Power_W: 100mW; TempCo: 100 ppm/C; Value_Code: 3k09; Value: 3.09k; EIA_Code: E96; SizeX_mm: 1.6; SizeY_mm: 0.8; SizeZ_mm: 1; Value2: 0.1W; SizeArea_mm2: 1.28; AEC Qualified: Y; VDC_V: 75V; AEC Category: Q200; AEC Grade: 0
R84 = CMP-0026915-3: RES, 39 k, 5%, 0.063 W, AEC-Q200 Grade 0, 0402; Manufacturer: Vishay-Dale; Power_W: 63mW; TempCo: 200 ppm/C; Value_Code: 39k0; Value: 39k; EIA_Code: E24; SizeX_mm: 1; SizeY_mm: 0.5; SizeZ_mm: 0.6; Value2: 0.063W; AEC Qualified: Y; VDC_V: 50V; AEC Category: Q200; AEC Grade: 0
R86 = CMP-0026963-3: RES, 68 k, 5%, 0.063 W, AEC-Q200 Grade 0, 0402; Manufacturer: Vishay-Dale; Power_W: 63mW; TempCo: 200 ppm/C; Value_Code: 68k0; Value: 68k; EIA_Code: E24; SizeX_mm: 1; SizeY_mm: 0.5; SizeZ_mm: 0.6; Value2: 0.063W; AEC Qualified: Y; VDC_V: 50V; AEC Category: Q200; AEC Grade: 0
R87 = CMP-0026966-5: RES, 6.8 k, 5%, 0.063 W, AEC-Q200 Grade 0, 0402; Manufacturer: Vishay-Dale; Power_W: 63mW; TempCo: 200 ppm/C; Value_Code: 6k80; Value: 6.8k; EIA_Code: E24; SizeX_mm: 1; SizeY_mm: 0.5; SizeZ_mm: 0.6; Value2: 0.063W; AEC Qualified: Y; VDC_V: 50V; AEC Category: Q200; AEC Grade: 0
R110 = CMP-0026193-2: RES, 249 k, 1%, 0.063 W, AEC-Q200 Grade 0, 0402; Manufacturer: Vishay-Dale; Power_W: 63mW; TempCo: 100 ppm/C; Value: 249k; EIA_Code: E96; SizeX_mm: 1; SizeY_mm: 0.5; SizeZ_mm: 0.6; Value2: 0.063W; AEC Qualified: Y; VDC_V: 50V; AEC Category: Q200; AEC Grade: 0
R111 R113 = CMP-0026823-3: RES, 100 k, 5%, 0.063 W, AEC-Q200 Grade 0, 0402; Manufacturer: Vishay-Dale; Power_W: 63mW; TempCo: 200 ppm/C; Value: 100k; EIA_Code: E24; SizeX_mm: 1; SizeY_mm: 0.5; SizeZ_mm: 0.6; Value2: 0.063W; AEC Qualified: Y; VDC_V: 50V; AEC Category: Q200; AEC Grade: 0
R112 = CMP-0026823-3: RES, 100 k, 5%, 0.063 W, AEC-Q200 Grade 0, 0402; Manufacturer: Vishay-Dale; Power_W: 63mW; TempCo: 200 ppm/C; Value: 100k; EIA_Code: E24; SizeX_mm: 1; SizeY_mm: 0.5; SizeZ_mm: 0.6; Value2: 0.063W; AEC Qualified: Y; VDC_V: 50V; AEC Grade: 0; AEC Category: Q200
R114 = CMP-0026852-3: RES, 1.0 k, 5%, 0.063 W, AEC-Q200 Grade 0, 0402; Manufacturer: Vishay-Dale; Power_W: 63mW; TempCo: 200 ppm/C; Value_Code: 1k00; Value: 1.0k; EIA_Code: E24; Res_ohm: 1k; SizeX_mm: 1; SizeY_mm: 0.5; SizeZ_mm: 0.6; Value2: 0.063W; AEC Qualified: Y; VDC_V: 50V; AEC Category: Q200; AEC Grade: 0
R115 = CMP-0026490-2: RES, 61.9 k, 1%, 0.063 W, AEC-Q200 Grade 0, 0402; Manufacturer: Vishay-Dale; Power_W: 63mW; TempCo: 100 ppm/C; Value_Code: 61k9; Value: 61.9k; EIA_Code: E96; SizeX_mm: 1; SizeY_mm: 0.5; SizeZ_mm: 0.6; Value2: 0.063W; AEC Qualified: Y; VDC_V: 50V; AEC Category: Q200; AEC Grade: 0
SH-J15-SH-J21 = CMP-0003761-2: Shunt, 2.54mm, Gold, Black; Manufacturer: Wurth Elektronik
U6 = CMP-0082641-1: Low-Drift Low-Power Small-Footprint Series Voltage Reference With Clean Start, DBV0005A (SOT-23-5); Alternate Manufacturer: Texas Instruments; SizeAreaWB_mm2: 14.82; Rating: Catalog; SizeZ_mm: 1.45; SizeX_mm: 2.8; SizeY_mm: 2.9; SizeArea_mm2: 8.12; CompType: IC; AEC Qualified: N; AEC Category: Q200
U19 = CMP-0065082-2: 700nA, Precision Zero-Drift Amplifier, DBV0005A (SOT-23-5); Manufacturer: Texas Instruments; Alternate PartNumber: LPV821DBVT; SizeX_mm: 2.8; SizeY_mm: 2.9; CompType: IC; SizeZ_mm: 1.45; SizeArea_mm2: 8.12; SizeAreaWB_mm2: 14.82; U/M: EA
U21 = CMP-0065258-3: Nanopower, Ultra-Small Size, Sensor Monitor with I2C Interface and Alert Output, RUG0010A (X2QFN-10); Manufacturer: Texas Instruments; Alternate PartNumber: ADS7142IRUGT; SizeX_mm: 1.5; SizeY_mm: 2.0; CompType: IC; SizeZ_mm: 0.4; SizeArea_mm2: 3.0; SizeAreaWB_mm2: 7.5; U/M: EA
U22 = CMP-0081218-1: Micro-Power (50 µA), Zero-Drift, Rail-to-Rail-Out Instrumentation Amplifier, DGK0008A (VSSOP-8); Alternate PartNumber: INA317IDGKT; Alternate Manufacturer: Texas Instruments; SizeAreaWB_mm2: 35.955; SizeZ_mm: 1.1; SizeX_mm: 5.05; SizeY_mm: 3.1; SizeArea_mm2: 15.655; CompType: IC; AEC Qualified: N; AEC Category: Q200
U23 = CMP-0081990-1: High-Accuracy, Low-Power, Digital Temperature Sensor With SMBus- and I2C-Compatible Interface, DRV0006B (WSON-6); Alternate PartNumber: TMP117AIDRVT; Alternate Manufacturer: Texas Instruments; SizeAreaWB_mm2: 9; SizeZ_mm: 0.8; SizeX_mm: 2; SizeArea_mm2: 4; CompType: IC; AEC Qualified: N; AEC Category: Q200
U24 = CMP-0076503-2: 0.5degC Accurate 2-pin Temperature Sensor with a Pulse Train Interface, LPG0002A (TO-92-2); Alternate Manufacturer: Texas Instruments; SizeX_mm: 4.0; CompType: IC; SizeAreaWB_mm2: 20.75; SizeZ_mm: 5.05; SizeY_mm: 3.15; U/M: EA; SizeArea_mm2: 12.6

## Sheet TC_RTD_CJC_QFN.SchDoc
size 431 x 279 mm; Date: Not shown in title block; ApprovedBy: Not shown in title block; CheckedBy: Not shown in title block; Author: Not shown in title block; CompanyName: Not shown in title block; Engineer: Not shown in title block; Organization: Not shown in title block; Address1: Not shown in title block; Address2: Not shown in title block; Address3: Not shown in title block; Address4: Not shown in title block; DocumentNumber: 2; Revision: Use project parameter SCH_Rev; SheetNumber: 2; SheetTotal: 9; PageSetup: Record=PageOptions¦CenterHorizontal=True¦CenterVertical=True¦PrintScale=1.00¦XCorrection=1.00¦YCorrection=1.00¦PrintKind=0¦BorderSize=5000000¦LeftOffset=0¦BottomOffset=0¦Orientation=2¦PaperLength=1000¦PaperWidth=1000¦Scale=100¦PaperSource=15¦PrintQuality=600¦MediaType=1¦DitherType=10¦PaperKind=Letter¦PrintScaleMode=1
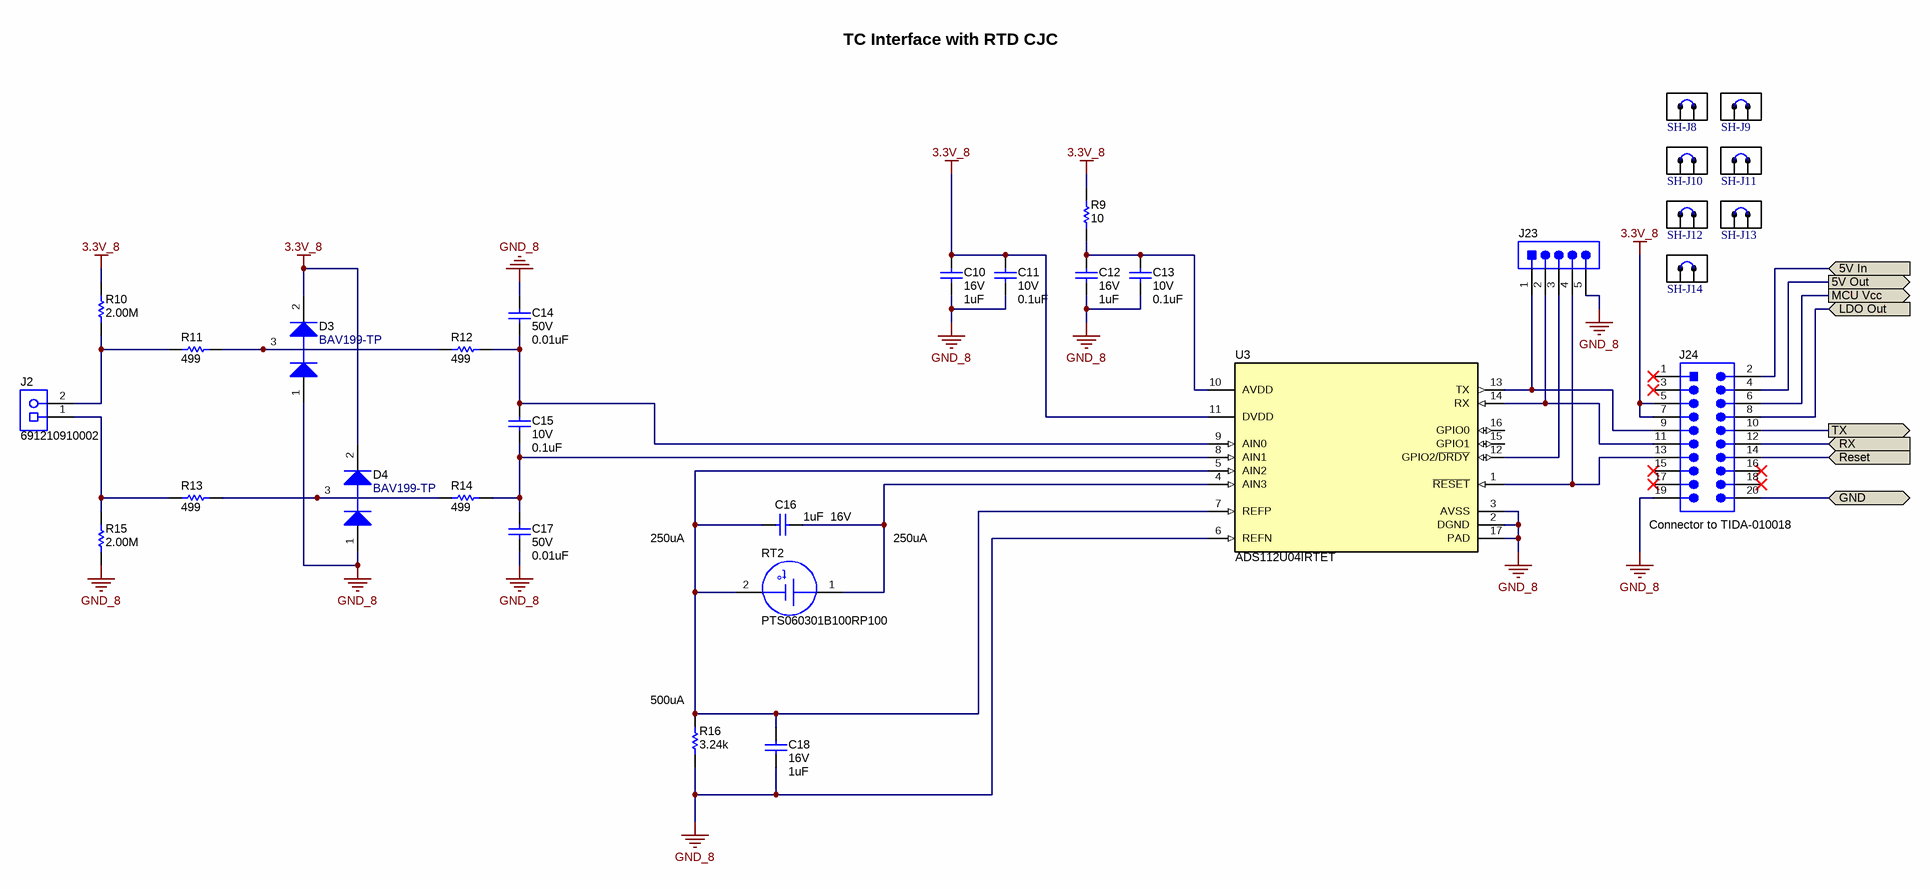
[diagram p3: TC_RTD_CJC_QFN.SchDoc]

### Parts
C10  VDC_V: 16V  ValueDisplayed: 1uF  [0603]  (hidden comment: 885012106017)
C11  VDC_V: 10V  ValueDisplayed: 0.1uF  [0603]  (hidden comment: 885012206020)
C12  VDC_V: 16V  ValueDisplayed: 1uF  [0603]  (hidden comment: 885012106017)
C13  VDC_V: 10V  ValueDisplayed: 0.1uF  [0603]  (hidden comment: 885012206020)
C14  VDC_V: 50V  ValueDisplayed: 0.01uF  [0603]  (hidden comment: C1608NP01H103J080AA)
C15  VDC_V: 10V  ValueDisplayed: 0.1uF  [0603]  (hidden comment: 885012206020)
C16  VDC_V: 16V  ValueDisplayed: 1uF  [0603]  (hidden comment: 885012106017)
C17  VDC_V: 50V  ValueDisplayed: 0.01uF  [0603]  (hidden comment: C1608NP01H103J080AA)
C18  VDC_V: 16V  ValueDisplayed: 1uF  [0603]  (hidden comment: 885012106017)
D3  BAV199-TP  [SOT-23L]
D4  BAV199-TP  [SOT-23L]
J2  691210910002  [Wurth_691210910002]
J23  61300511121  [Wurth_61300511121]  (value not drawn)
J24  PRPC010DAAN-RC  [Sullins_xxxC010DAAN]  (value not drawn)
R9  ValueDisplayed: 10  [0402]  (hidden comment: CRCW040210R0JNED)
R10  ValueDisplayed: 2.00M  [0402]  (hidden comment: CRCW04022M00FKED)
R11  ValueDisplayed: 499  [0402]  (hidden comment: CRCW0402499RFKED)
R12  ValueDisplayed: 499  [0402]  (hidden comment: CRCW0402499RFKED)
R13  ValueDisplayed: 499  [0402]  (hidden comment: CRCW0402499RFKED)
R14  ValueDisplayed: 499  [0402]  (hidden comment: CRCW0402499RFKED)
R15  ValueDisplayed: 2.00M  [0402]  (hidden comment: CRCW04022M00FKED)
R16  ValueDisplayed: 3.24k  [1206]  (hidden comment: PFC-W1206R-12-3241-B)
RT2  PTS060301B100RP100  [0603S]
SH-J8  60900213421  [Wurth_60900213421]  (value not drawn)
SH-J9  60900213421  [Wurth_60900213421]  (value not drawn)
SH-J10  60900213421  [Wurth_60900213421]  (value not drawn)
SH-J11  60900213421  [Wurth_60900213421]  (value not drawn)
SH-J12  60900213421  [Wurth_60900213421]  (value not drawn)
SH-J13  60900213421  [Wurth_60900213421]  (value not drawn)
SH-J14  60900213421  [Wurth_60900213421]  (value not drawn)
U3  ADS112U04IRTET  [RTE0016D]

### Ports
5V In (in), 5V Out (out), GND (bidir), LDO Out (in), MCU Vcc (out), Reset (in), RX (in), TX (out)

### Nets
3.3V: J24.6 ; port MCU Vcc
3.3V_8: C10.1 C11.1 D3.2(K) D4.2(K) J24.5 J24.7 R9.2 R10.2 U3.11(DVDD)
GND: J24.20 ; port GND
GND_8: C10.2 C11.2 C12.2 C13.2 C14.2 C17.2 C18.2 D3.1(A) D4.1(A) J23.5 J24.19 R15.1 R16.1 U3.2(DGND) U3.3(AVSS) U3.6(REFN) U3.17(PAD)
NetC12_1: C12.1 C13.1 R9.1 U3.10(AVDD)
NetC14_1: C14.1 C15.1 R12.1 U3.9(AIN0)
NetC15_2: C15.2 C17.1 R14.1 U3.8(AIN1)
NetC16_1: C16.1 C18.1 R16.2 RT2.2(-) U3.5(AIN2) U3.7(REFP)
NetC16_2: C16.2 RT2.1(+) U3.4(AIN3)
NetC83_3_1: J24.4 ; port 5V Out
NetC84_3_1: J24.8 ; port LDO Out
NetC89_3_1: J24.2 ; port 5V In
NetD3_3: D3.3(C) R11.1 R12.2
NetD4_3: D4.3(C) R13.1 R14.2
NetJ2_1: J2.1 R13.2 R15.2
NetJ2_2: J2.2 R10.1 R11.2
NetJ23_1: J23.1 J24.9 U3.13(TX)
NetJ23_2: J23.2 J24.11 U3.14(RX)
NetJ23_3: J23.3 U3.12(GPIO2/~{DRDY})
NetJ23_4: J23.4 J24.13 U3.1(~{RESET})
NetJ24_10: J24.10 ; port TX
NetJ24_12: J24.12 ; port RX
NetJ24_14: J24.14 ; port Reset

Not connected (* = marked no-connect by the designer): J24 1* 3* 15* 16* 17* 18*; U3 15(GPIO1) 16(GPIO0)

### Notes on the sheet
- TC Interface with RTD CJC
- 250uA
- (near J24) Connector to TIDA-010018
- (near R16) 500uA

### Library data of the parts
C10 C12 C16 C18 = CMP-0006824-5: as C54 on sheet TC_INA_ADS7142
C11 C13 C15 = CMP-0064931-4: as C1 on sheet TC_INA_ADS7142
C14 C17 = CMP-0006998-4: CAP, CERM, 0.01 uF, 50 V, +/- 5%, C0G/NP0, 0603; Manufacturer: TDK; TaMin_C: -55°C; Polarized: N; SizeAreaWB_mm2: 4.68; Value1: Unknown; U/M: EA; Value: 0.01uF; TaMax_C: 150°C; SizeZ_mm: 1; SizeX_mm: 1.6; SizeY_mm: 0.8; SizeArea_mm2: 1.28; Cap_F: 10nF; AEC Category: Q200
D3 D4 = CMP-0076968-2: as D12 on sheet TC_INA_ADS7142
J2 = CMP-0082072-1: as J31 on sheet TC_INA_ADS7142
J23 = CMP-0084909-1: as J28 on sheet TC_INA_ADS7142
J24 = CMP-0054591-2: as J22 on sheet TC_INA_ADS7142
R9 = CMP-0026827-3: as R4 on sheet TC_INA_ADS7142
R10 R15 = CMP-0026245-2: as R73 on sheet TC_INA_ADS7142
R11-R14 = CMP-0026402-2: as R76 on sheet TC_INA_ADS7142
R16 = CMP-0018789-2: RES, 3.24 k, 0.1%, 0.333 W, 1206; Manufacturer: TT Electronics/IRC; Power_W: 333mW; TempCo: 10 ppm/C; Value_Code: 3k24; U/M: EA; Value: 3.24k; EIA_Code: E192; SizeX_mm: 3.2; SizeY_mm: 1.6; SizeZ_mm: 1.35; Value2: 0.333W; SizeArea_mm2: 5.12; AEC Category: Q200
RT2 = CMP-0001709-3: Temperature Sensor 100 ohm, SMD; Manufacturer: Vishay/Beyschlag; Value: 100ohm; SizeX_mm: 1.6; SizeY_mm: 0.8; CompType: Temp Sensor; SizeZ_mm: 1; SizeArea_mm2: 1.28; SizeAreaWB_mm2: 4.68
SH-J8-SH-J14 = CMP-0003761-2: as SH-J15 on sheet TC_INA_ADS7142
U3 = CMP-0078503-1: 16-Bit, 4-Channel, 2-kSPS, Delta-Sigma ADC with UART Interface, RTE0016D (WQFN-16); Alternate PartNumber: ADS112U04IRTER; Alternate Manufacturer: Texas Instruments; SizeAreaWB_mm2: 16; SizeZ_mm: 0.8; SizeX_mm: 3; SizeArea_mm2: 9; CompType: IC; AEC Qualified: N; AEC Category: Q200

## Sheet TC_LMT70_CJC.SchDoc
size 431 x 279 mm; Date: Not shown in title block; ApprovedBy: Not shown in title block; CheckedBy: Not shown in title block; Author: Not shown in title block; CompanyName: Not shown in title block; Engineer: Not shown in title block; Organization: Not shown in title block; Address1: Not shown in title block; Address2: Not shown in title block; Address3: Not shown in title block; Address4: Not shown in title block; DocumentNumber: 3; Revision: Use project parameter SCH_Rev; SheetNumber: 3; SheetTotal: 9; PageSetup: Record=PageOptions¦CenterHorizontal=True¦CenterVertical=True¦PrintScale=1.00¦XCorrection=1.00¦YCorrection=1.00¦PrintKind=0¦BorderSize=5000000¦LeftOffset=0¦BottomOffset=0¦Orientation=2¦PaperLength=1000¦PaperWidth=1000¦Scale=100¦PaperSource=15¦PrintQuality=600¦MediaType=1¦DitherType=10¦PaperKind=Letter¦PrintScaleMode=1
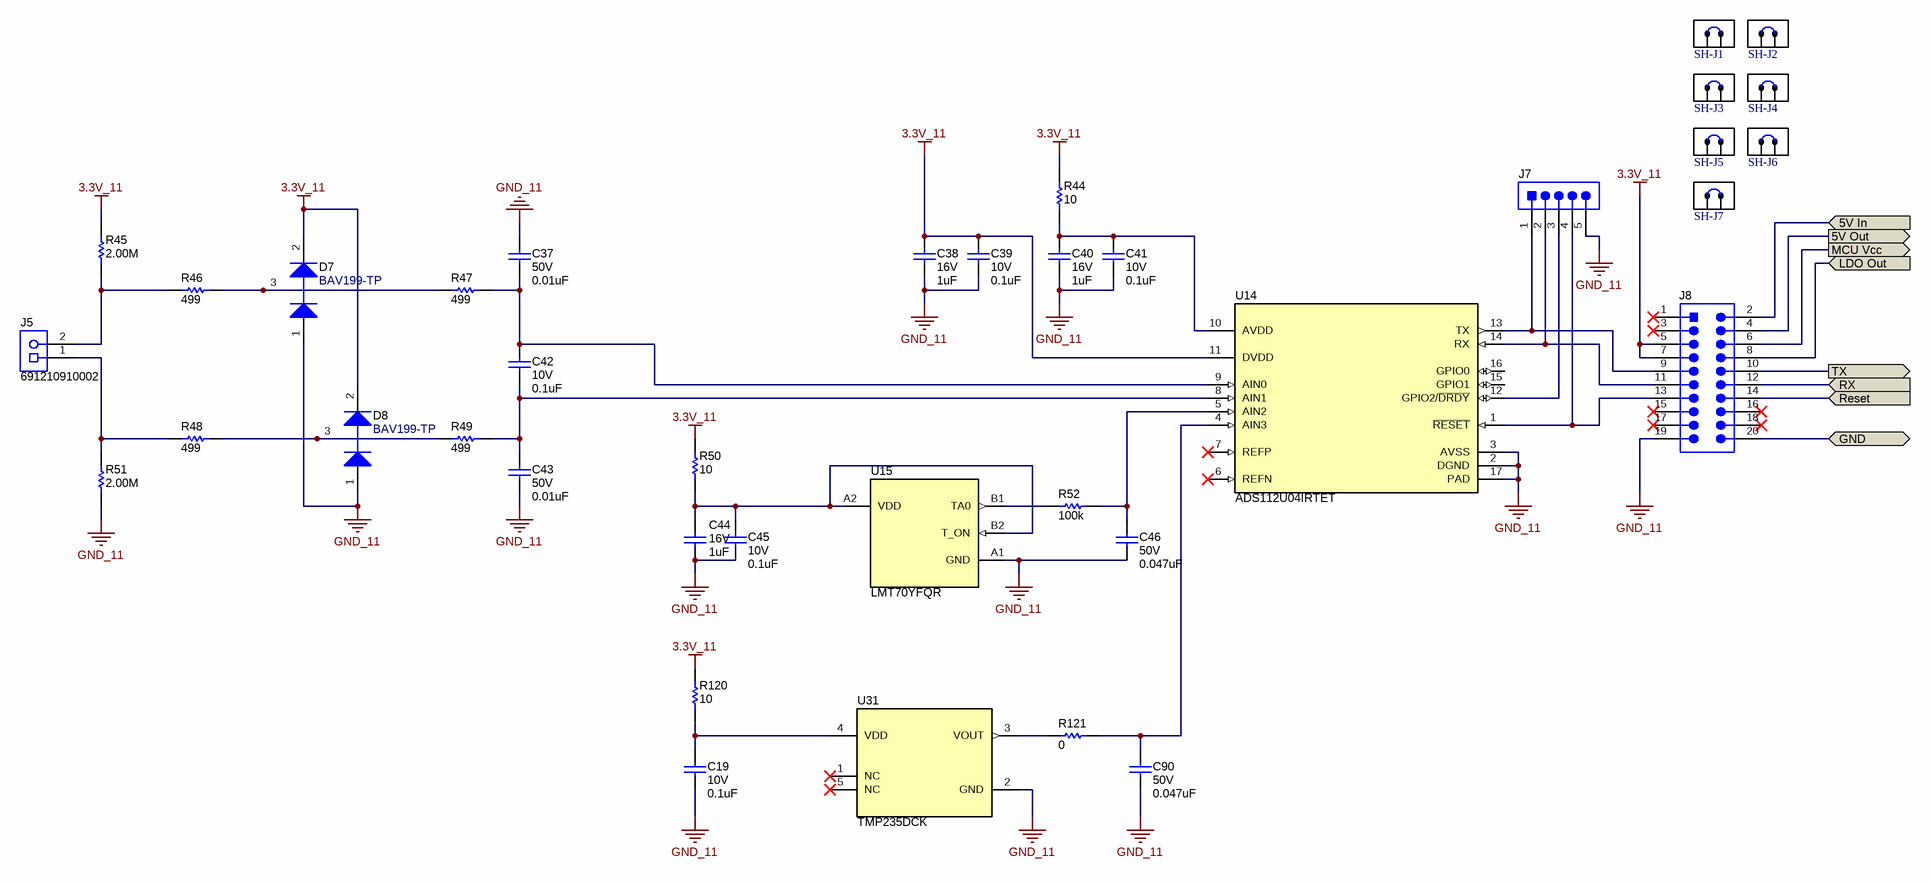
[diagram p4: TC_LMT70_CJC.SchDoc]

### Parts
C19  VDC_V: 10V  ValueDisplayed: 0.1uF  [0603]  (hidden comment: 885012206020)
C37  VDC_V: 50V  ValueDisplayed: 0.01uF  [0603]  (hidden comment: C1608NP01H103J080AA)
C38  VDC_V: 16V  ValueDisplayed: 1uF  [0603]  (hidden comment: 885012106017)
C39  VDC_V: 10V  ValueDisplayed: 0.1uF  [0603]  (hidden comment: 885012206020)
C40  VDC_V: 16V  ValueDisplayed: 1uF  [0603]  (hidden comment: 885012106017)
C41  VDC_V: 10V  ValueDisplayed: 0.1uF  [0603]  (hidden comment: 885012206020)
C42  VDC_V: 10V  ValueDisplayed: 0.1uF  [0603]  (hidden comment: 885012206020)
C43  VDC_V: 50V  ValueDisplayed: 0.01uF  [0603]  (hidden comment: C1608NP01H103J080AA)
C44  VDC_V: 16V  ValueDisplayed: 1uF  [0603]  (hidden comment: 885012106017)
C45  VDC_V: 10V  ValueDisplayed: 0.1uF  [0603]  (hidden comment: 885012206020)
C46  VDC_V: 50V  ValueDisplayed: 0.047uF  [0603]  (hidden comment: C1608X5R1H473K080AA)
C90  VDC_V: 50V  ValueDisplayed: 0.047uF  [0603]  (hidden comment: C1608X5R1H473K080AA)
D7  BAV199-TP  [SOT-23L]
D8  BAV199-TP  [SOT-23L]
J5  691210910002  [Wurth_691210910002]
J7  61300511121  [Wurth_61300511121]  (value not drawn)
J8  PRPC010DAAN-RC  [Sullins_xxxC010DAAN]  (value not drawn)
R44  ValueDisplayed: 10  [0402]  (hidden comment: CRCW040210R0JNED)
R45  ValueDisplayed: 2.00M  [0402]  (hidden comment: CRCW04022M00FKED)
R46  ValueDisplayed: 499  [0402]  (hidden comment: CRCW0402499RFKED)
R47  ValueDisplayed: 499  [0402]  (hidden comment: CRCW0402499RFKED)
R48  ValueDisplayed: 499  [0402]  (hidden comment: CRCW0402499RFKED)
R49  ValueDisplayed: 499  [0402]  (hidden comment: CRCW0402499RFKED)
R50  ValueDisplayed: 10  [0402]  (hidden comment: CRCW040210R0JNED)
R51  ValueDisplayed: 2.00M  [0402]  (hidden comment: CRCW04022M00FKED)
R52  ValueDisplayed: 100k  [0402]  (hidden comment: CRCW0402100KFKED)
R120  ValueDisplayed: 10  [0402]  (hidden comment: CRCW040210R0JNED)
R121  ValueDisplayed: 0  [0402]  (hidden comment: CRCW04020000Z0EDHP)
SH-J1  60900213421  [Wurth_60900213421]  (value not drawn)
SH-J2  60900213421  [Wurth_60900213421]  (value not drawn)
SH-J3  60900213421  [Wurth_60900213421]  (value not drawn)
SH-J4  60900213421  [Wurth_60900213421]  (value not drawn)
SH-J5  60900213421  [Wurth_60900213421]  (value not drawn)
SH-J6  60900213421  [Wurth_60900213421]  (value not drawn)
SH-J7  60900213421  [Wurth_60900213421]  (value not drawn)
U14  ADS112U04IRTET  [RTE0016D]
U15  LMT70YFQR  [YFQ0004ACAC]
U31  TMP235DCK  [DCK0005A_N]

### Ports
5V In (in), 5V Out (out), GND (bidir), LDO Out (in), MCU Vcc (out), Reset (in), RX (in), TX (out)

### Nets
3.3V: J8.6 ; port MCU Vcc
3.3V_11: C38.1 C39.1 D7.2(K) D8.2(K) J8.5 J8.7 R44.2 R45.2 R50.2 R120.2 U14.11(DVDD)
GND: J8.20 ; port GND
GND_11: C19.2 C37.2 C38.2 C39.2 C40.2 C41.2 C43.2 C44.2 C45.2 C46.2 C90.2 D7.1(A) D8.1(A) J7.5 J8.19 R51.1 U14.2(DGND) U14.3(AVSS) U14.17(PAD) U15.A1(GND) U31.2(GND)
NetC19_1: C19.1 R120.1 U31.4(VDD)
NetC37_1: C37.1 C42.1 R47.1 U14.9(AIN0)
NetC40_1: C40.1 C41.1 R44.1 U14.10(AVDD)
NetC42_2: C42.2 C43.1 R49.1 U14.8(AIN1)
NetC44_1: C44.1 C45.1 R50.1 U15.A2(VDD) U15.B2(T_ON)
NetC46_1: C46.1 R52.1 U14.5(AIN2)
NetC83_4_1: J8.4 ; port 5V Out
NetC84_4_1: J8.8 ; port LDO Out
NetC89_4_1: J8.2 ; port 5V In
NetC90_1: C90.1 R121.1 U14.4(AIN3)
NetD7_3: D7.3(C) R46.1 R47.2
NetD8_3: D8.3(C) R48.1 R49.2
NetJ5_1: J5.1 R48.2 R51.2
NetJ5_2: J5.2 R45.1 R46.2
NetJ7_1: J7.1 J8.9 U14.13(TX)
NetJ7_2: J7.2 J8.11 U14.14(RX)
NetJ7_3: J7.3 U14.12(GPIO2/~{DRDY})
NetJ7_4: J7.4 J8.13 U14.1(~{RESET})
NetJ8_10: J8.10 ; port TX
NetJ8_12: J8.12 ; port RX
NetJ8_14: J8.14 ; port Reset
NetR52_2: R52.2 U15.B1(TA0)
NetR121_2: R121.2 U31.3(VOUT)

Not connected (* = marked no-connect by the designer): J8 1* 3* 15* 16* 17* 18*; U14 6(REFN)* 7(REFP)* 15(GPIO1) 16(GPIO0); U31 1(NC)* 5(NC)*

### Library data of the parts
C19 C39 C41 C42 C45 = CMP-0064931-4: as C1 on sheet TC_INA_ADS7142
C37 C43 = CMP-0006998-4: as C14 on sheet TC_RTD_CJC_QFN
C38 C40 C44 = CMP-0006824-5: as C54 on sheet TC_INA_ADS7142
C46 C90 = CMP-0007015-5: CAP, CERM, 0.047 uF, 50 V, +/- 10%, X5R, 0603; Manufacturer: TDK; TaMin_C: -55°C; ESR_ohm: 0.049007; Polarized: N; SizeAreaWB_mm2: 4.68; Value1: 0.049007 ohm; U/M: EA; TaMax_C: 85°C; SizeZ_mm: 1; SizeX_mm: 1.6; SizeY_mm: 0.8; SizeArea_mm2: 1.28; Cap_F: 47nF; IRMS_A: 767.528mA; AEC Category: Q200
D7 D8 = CMP-0076968-2: as D12 on sheet TC_INA_ADS7142
J5 = CMP-0082072-1: as J31 on sheet TC_INA_ADS7142
J7 = CMP-0084909-1: as J28 on sheet TC_INA_ADS7142
J8 = CMP-0054591-2: as J22 on sheet TC_INA_ADS7142
R44 R50 R120 = CMP-0026827-3: as R4 on sheet TC_INA_ADS7142
R45 R51 = CMP-0026245-2: as R73 on sheet TC_INA_ADS7142
R46-R49 = CMP-0026402-2: as R76 on sheet TC_INA_ADS7142
R52 = CMP-0025950-3: as R6 on sheet TC_INA_ADS7142
R121 = CMP-0081856-1: RES, 0, 0%, 0.2 W, AEC-Q200 Grade 0, 0402; Manufacturer: Vishay-Dale; SizeAreaWB_mm2: 3; SizeArea_mm2: 0.5; AEC Qualified: Y; AEC Category: Q200; Value: 0; SizeZ_mm: 0.6; Power_W: 200mW; VDC_V: 50V; Value2: 0.2W; SizeX_mm: 1
SH-J1-SH-J7 = CMP-0003761-2: as SH-J15 on sheet TC_INA_ADS7142
U14 = CMP-0078503-1: as U3 on sheet TC_RTD_CJC_QFN
U15 = CMP-0066231-1: +/-0.1degC Precision Analog Temperature Sensor, YFQ0004ACAC (DSBGA-4); Alternate PartNumber: LMT70YFQT; Alternate Manufacturer: Texas Instruments; SizeAreaWB_mm2: 3.549456; U/M: EA; SizeZ_mm: 0.675; SizeX_mm: 0.884; SizeArea_mm2: 0.781456; CompType: IC
U31 = CMP-0013250-3: TMP235DCK, DCK0005A (SOT-5); Manufacturer: Texas Instruments; SizeX_mm: 2.1; SizeY_mm: 2.0; CompType: IC; SizeZ_mm: 1.1; SizeArea_mm2: 4.2; SizeAreaWB_mm2: 9.3; AEC Category: Q200; AEC Qualified: N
